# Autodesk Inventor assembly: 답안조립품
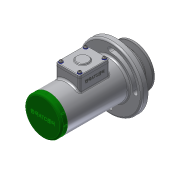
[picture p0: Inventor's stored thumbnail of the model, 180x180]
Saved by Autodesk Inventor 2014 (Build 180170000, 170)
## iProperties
Created: 2017-05
Part Number: 답안조립품
Document SubType Name: Assembly
Designer: user
Author: user
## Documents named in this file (20)
- C:\Users\user\Desktop\470508V1006\답안조립품.iam
- C:\Users\user\Desktop\470508V1006\본체.ipt
- C:\Users\user\Desktop\470508V1006\V-벨트풀리.ipt
- C:\Users\user\Desktop\470508V1006\너트 M10.ipt
- C:\Users\user\Desktop\470508V1006\멈춤링 15 x 1.ipt
- C:\Users\user\Desktop\470508V1006\멈춤링 35x1.6.ipt
- C:\Users\user\Desktop\470508V1006\베어링 15 x 35 x 11.ipt
- C:\Users\user\Desktop\470508V1006\볼트 M4 x 10.ipt
- C:\Users\user\Desktop\470508V1006\부시1.ipt
- C:\Users\user\Desktop\470508V1006\부시2.ipt
- C:\Users\user\Desktop\470508V1006\사이드 커버.ipt
- 사이드 커버.ipt
- C:\Users\user\Desktop\470508V1006\십자볼트 M3 x 10.ipt
- C:\Users\user\Desktop\470508V1006\오일 실 15 25 7.ipt
- C:\Users\user\Desktop\470508V1006\와셔 3x6.ipt
- C:\Users\user\Desktop\470508V1006\와셔 4x16.ipt
- C:\Users\user\Desktop\470508V1006\와셔 10x21.ipt
- C:\Users\user\Desktop\470508V1006\축.ipt
- C:\Users\user\Desktop\470508V1006\키 4 x 4 x 18.ipt
- C:\Users\user\Desktop\470508V1006\탑 커버.ipt
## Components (2 placed, 2 different names)
1. V-벨트풀리:1
2. ISO 4017 M4 x 10:1
## Named parameters: d26_d25 = 0, d27_d25 = 0, d28_d25 = 0
